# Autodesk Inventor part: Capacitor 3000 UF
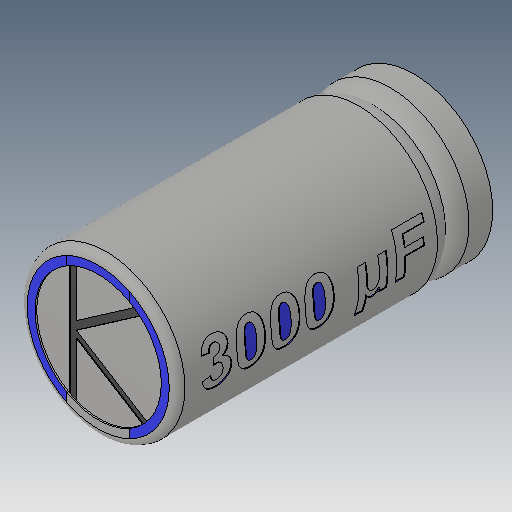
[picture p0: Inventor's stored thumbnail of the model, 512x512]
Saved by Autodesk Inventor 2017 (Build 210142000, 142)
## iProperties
Created: 2005-12
Part Number: Capacitor 3000 UF
Material: Generic
Document SubType Name: Modeling
Designer: DanielSeverino
Density: 1 g/cm^3
Appearance: Default
Author: DanielSeverino
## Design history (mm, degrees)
feature "Solid1"
body "Solid2"
